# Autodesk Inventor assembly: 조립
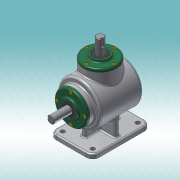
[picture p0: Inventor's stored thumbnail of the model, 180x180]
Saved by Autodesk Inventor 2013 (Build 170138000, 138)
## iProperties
Created: 2016-09
Part Number: 조립
Document SubType Name: Assembly
Designer: dgall
Author: dgall
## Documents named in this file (14)
- C:\Users\dgall\Desktop\460907V1007\조립.iam
- C:\Users\dgall\Desktop\460907V1007\본체.ipt
- C:\Users\dgall\Desktop\460907V1007\M4.ipt
- C:\Users\dgall\Desktop\460907V1007\메인 베벨기어.ipt
- C:\Users\dgall\Desktop\460907V1007\메인 축.ipt
- 메인 축.ipt
- C:\Users\dgall\Desktop\460907V1007\베어링 6203.ipt
- C:\Users\dgall\Desktop\460907V1007\서브 베벨기어.ipt
- C:\Users\dgall\Desktop\460907V1007\서브 축.ipt
- 서브 축.ipt
- C:\Users\dgall\Desktop\460907V1007\오일실 17 32 8.ipt
- C:\Users\dgall\Desktop\460907V1007\커버.ipt
- C:\Users\dgall\Desktop\460907V1007\키 4x4.ipt
- C:\Users\dgall\Desktop\460907V1007\키 5x5.ipt
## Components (8 placed, 1 different names)
1. M4:1
2. M4:3
3. M4:4
4. M4:5
5. M4:2
6. M4:6
7. M4:7
8. M4:8
